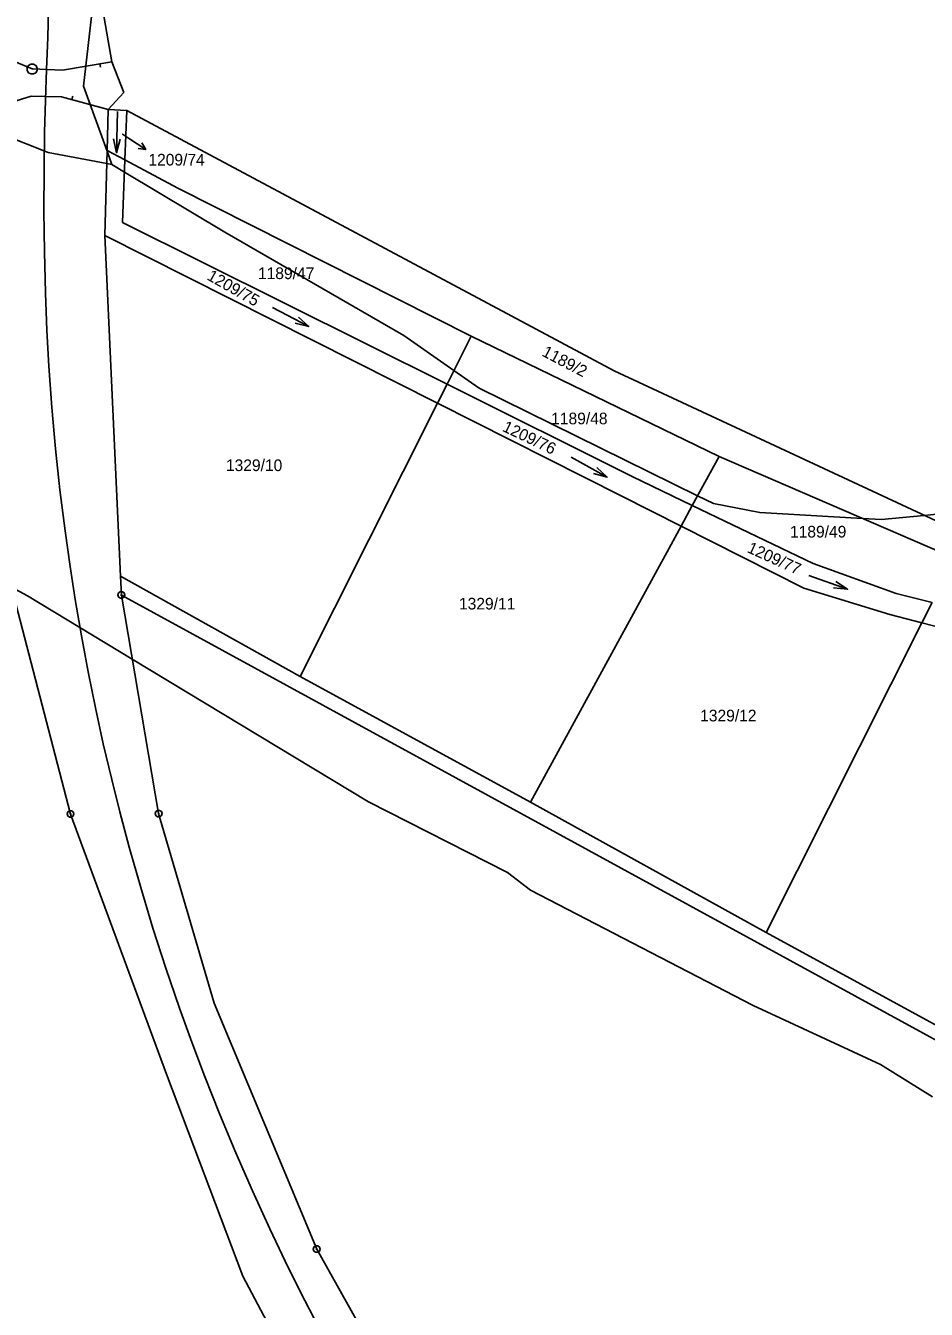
# Model space of a CAD drawing. Extents: x -789470 to -786707, y -1118640 to -1114455.
# Drawn here: x -787706 to -787574.7, y -1116838.5 to -1116651.3 of the extents above; entities that cross this region are included whole.
import ezdxf

# ---------------------------------------------------------------- set-up
doc = ezdxf.new("R2010")
doc.units = 0
for name, color, linetype in [('1', 7, 'Continuous'), ('11', 7, 'Continuous'), ('13', 7, 'Continuous'), ('2', 7, 'Continuous'), ('3', 7, 'Continuous'), ('6', 7, 'Continuous'), ('7', 7, 'Continuous'), ('8', 7, 'Continuous')]:
    doc.layers.add(name, color=color, linetype=linetype)

msp = doc.modelspace()

# ---------------------------------------------------------------- linework, layer by layer
at = {"layer": '1'}
for p, q in [((-787693.44, -1116656.57), (-787695.13, -1116646.88)), ((-787691.68, -1116661.08), (-787693.44, -1116656.57)), ((-787693.98, -1116663.52), (-787691.68, -1116661.08)), ((-787694.14, -1116669.51), (-787693.98, -1116663.52)), ((-787693.98, -1116663.52), (-787691.26, -1116663.69)), ((-787691.26, -1116663.69), (-787691.54, -1116670.9)), ((-787620.18, -1116701.66), (-787691.26, -1116663.69)), ((-787694.47, -1116681.92), (-787694.14, -1116669.51)), ((-787694.14, -1116669.51), (-787691.54, -1116670.9)), ((-787691.54, -1116670.9), (-787691.9, -1116680.01)), ((-787691.54, -1116670.9), (-787683.83, -1116675.03)), ((-787683.83, -1116675.03), (-787641.02, -1116696.6)), ((-787691.9, -1116680.01), (-787644.55, -1116703.62)), ((-787692.19, -1116731.59), (-787694.47, -1116681.92)), ((-787694.47, -1116681.92), (-787645.94, -1116706.39)), ((-787641.02, -1116696.6), (-787644.55, -1116703.62)), ((-787641.02, -1116696.6), (-787604.89, -1116714.14)), ((-787566.04, -1116726.9), (-787620.18, -1116701.66)), ((-787644.55, -1116703.62), (-787645.94, -1116706.39)), ((-787644.55, -1116703.62), (-787617.56, -1116717.08)), ((-787645.94, -1116706.39), (-787665.96, -1116746.26)), ((-787645.94, -1116706.39), (-787619.16, -1116719.89)), ((-787604.89, -1116714.14), (-787608.79, -1116721.29)), ((-787604.89, -1116714.14), (-787570.53, -1116728.97)), ((-787617.56, -1116717.08), (-787608.79, -1116721.29)), ((-787619.16, -1116719.89), (-787610.43, -1116724.3)), ((-787608.79, -1116721.29), (-787610.43, -1116724.3)), ((-787608.79, -1116721.29), (-787591.18, -1116729.74)), ((-787610.43, -1116724.3), (-787632.39, -1116764.58)), ((-787610.43, -1116724.3), (-787592.5, -1116733.37)), ((-787591.18, -1116729.74), (-787579.06, -1116734.12)), ((-787665.96, -1116746.26), (-787692.19, -1116731.59)), ((-787692.06, -1116734.36), (-787692.19, -1116731.59)), ((-787592.5, -1116733.37), (-787579.96, -1116737.21)), ((-787566.04, -1116803.25), (-787692.06, -1116734.36)), ((-787686.63, -1116766.25), (-787692.06, -1116734.36)), ((-787579.06, -1116734.12), (-787573.79, -1116735.43)), ((-787573.79, -1116735.43), (-787575.29, -1116738.41)), ((-787707.44, -1116735.64), (-787699.48, -1116766.3)), ((-787579.96, -1116737.21), (-787575.29, -1116738.41)), ((-787575.29, -1116738.41), (-787598.03, -1116783.56)), ((-787575.29, -1116738.41), (-787546.01, -1116745.93)), ((-787632.39, -1116764.58), (-787665.96, -1116746.26)), ((-787598.03, -1116783.56), (-787632.39, -1116764.58)), ((-787699.48, -1116766.3), (-787685.49, -1116804.26)), ((-787678.51, -1116793.87), (-787686.63, -1116766.25)), ((-787564.65, -1116801.84), (-787598.03, -1116783.56)), ((-787663.57, -1116829.76), (-787678.51, -1116793.87)), ((-787685.49, -1116804.26), (-787674.36, -1116833.72)), ((-787646.12, -1116860.74), (-787663.57, -1116829.76)), ((-787674.36, -1116833.72), (-787653.7, -1116872.34))]:
    msp.add_line(p, q, dxfattribs=at)
at = {"layer": '11'}
for points in [[(-787693.43, -1116671.58), (-787694.19, -1116671.43), (-787702.73, -1116669.8), (-787712.93, -1116665.78), (-787750.01, -1116651.19), (-787761.1, -1116647.27), (-787763.53, -1116646.41), (-787769.34, -1116643.04), (-787790.93, -1116630.52), (-787799.79, -1116626.21), (-787809.71, -1116621.47)], [(-787696.22, -1116648.29), (-787697.58, -1116660.12), (-787694.14, -1116669.61), (-787693.43, -1116671.58)], [(-787466.76, -1116688.14), (-787500, -1116682.32), (-787501.54, -1116682.05), (-787515.69, -1116684.6), (-787519.49, -1116685.93), (-787526.3, -1116688.31), (-787533.54, -1116692.9), (-787534.66, -1116693.74), (-787542.48, -1116699.58), (-787561.24, -1116718.02), (-787567.61, -1116720.5), (-787573.13, -1116722.56), (-787574.97, -1116722.74), (-787581.18, -1116723.33), (-787583.95, -1116723.18), (-787598.96, -1116722.33), (-787605.72, -1116721), (-787608.02, -1116719.87), (-787639.89, -1116704.2), (-787643.55, -1116701.62), (-787650.84, -1116696.49), (-787676.99, -1116681.45), (-787691.61, -1116672.67), (-787693.43, -1116671.58)], [(-787758.46, -1116706.09), (-787742.14, -1116714.87), (-787708.07, -1116733.22), (-787705.74, -1116734.47), (-787690.47, -1116743.7), (-787656, -1116764.52), (-787635.75, -1116774.85), (-787632.38, -1116777.42), (-787599.9, -1116794.21), (-787581.34, -1116802.84), (-787573.75, -1116807.56)]]:
    msp.add_lwpolyline(points, dxfattribs=at)
at = {"layer": '13'}
for p, q in [((-787711.9, -1116654.76), (-787705.05, -1116657.63)), ((-787700.64, -1116657.78), (-787693.44, -1116656.57)), ((-787695.22, -1116656.87), (-787695.13, -1116657.36)), ((-787693.44, -1116656.57), (-787691.68, -1116661.08)), ((-787705.05, -1116657.63), (-787700.64, -1116657.78)), ((-787705.21, -1116661.61), (-787713, -1116663.97)), ((-787700.79, -1116661.69), (-787705.21, -1116661.61)), ((-787693.98, -1116663.52), (-787700.79, -1116661.69)), ((-787699.29, -1116662.09), (-787699.16, -1116661.61)), ((-787691.68, -1116661.08), (-787693.98, -1116663.52))]:
    msp.add_line(p, q, dxfattribs=at)
at = {"layer": '3'}
for p, q in [((-787692.65, -1116663.84), (-787692.77, -1116669.84)), ((-787670.02, -1116692.4), (-787664.72, -1116695.2)), ((-787626.45, -1116714.24), (-787621.21, -1116717.18)), ((-787591.78, -1116731.5), (-787586.14, -1116733.52))]:
    msp.add_line(p, q, dxfattribs=at)
for points in [[(-787692.23, -1116667.85), (-787692.77, -1116669.84), (-787693.23, -1116667.83)], [(-787666.25, -1116693.83), (-787664.72, -1116695.2), (-787666.72, -1116694.71)], [(-787622.71, -1116715.76), (-787621.21, -1116717.18), (-787623.2, -1116716.64)], [(-787587.85, -1116732.38), (-787586.14, -1116733.52), (-787588.19, -1116733.32)]]:
    msp.add_lwpolyline(points, dxfattribs=at)
at = {"layer": '6'}
msp.add_line((-787702.06, -1116625.08), (-787702.77, -1116653), dxfattribs=at)
for points in [[(-787702.77, -1116653), (-787702.99, -1116657.73), (-787703.14, -1116662.17), (-787703.26, -1116666.91), (-787703.34, -1116672.4), (-787703.35, -1116678.36), (-787703.27, -1116684.32), (-787703.12, -1116690.27), (-787702.91, -1116695.76)], [(-787702.91, -1116695.76), (-787702.63, -1116700.98), (-787702.2, -1116707), (-787701.66, -1116713.02), (-787701.02, -1116719.02), (-787700.27, -1116725.02), (-787699.54, -1116730.19), (-787698.79, -1116735.02), (-787697.89, -1116740.3), (-787696.91, -1116745.56), (-787695.84, -1116750.81), (-787694.7, -1116756.05), (-787693.47, -1116761.26), (-787692.28, -1116766)], [(-787692.28, -1116766), (-787690.92, -1116771.12), (-787689.24, -1116777.04), (-787687.45, -1116782.93), (-787685.56, -1116788.79), (-787683.57, -1116794.62), (-787681.77, -1116799.6), (-787679.92, -1116804.51), (-787677.7, -1116810.14), (-787675.37, -1116815.73), (-787672.95, -1116821.28), (-787670.43, -1116826.79), (-787668.17, -1116831.52)], [(-787668.17, -1116831.52), (-787665.94, -1116836.02), (-787663.36, -1116841.02), (-787660.71, -1116845.97), (-787657.98, -1116850.88), (-787655.16, -1116855.74), (-787652.27, -1116860.56), (-787649.62, -1116864.83), (-787646.87, -1116869.14), (-787643.67, -1116873.96), (-787640.4, -1116878.73), (-787637.04, -1116883.45), (-787633.61, -1116888.11), (-787630.1, -1116892.71), (-787626.94, -1116896.72)]]:
    msp.add_lwpolyline(points, dxfattribs=at)
at = {"layer": '7'}
for p in [(-787691.92, -1116667.15), (-787688.51, -1116669.37)]:
    msp.add_line(p, (-787691.02, -1116667.73), dxfattribs=at)
msp.add_lwpolyline([(-787689.07, -1116668.4), (-787688.51, -1116669.37), (-787689.62, -1116669.24)], dxfattribs=at)
at = {"layer": '8'}
for p, q in [((-787705.1, -1116657.63), (-787705, -1116657.63)), ((-787692.18, -1116734.36), (-787691.94, -1116734.36)), ((-787699.6, -1116766.3), (-787699.36, -1116766.3)), ((-787686.75, -1116766.25), (-787686.51, -1116766.25)), ((-787663.69, -1116829.76), (-787663.45, -1116829.76))]:
    msp.add_line(p, q, dxfattribs=at)
for points in [[(-787704.86, -1116656.91), (-787704.52, -1116657.1), (-787704.33, -1116657.44), (-787704.33, -1116657.83), (-787704.52, -1116658.17), (-787704.86, -1116658.36), (-787705.25, -1116658.36), (-787705.59, -1116658.17), (-787705.78, -1116657.83), (-787705.78, -1116657.44), (-787705.59, -1116657.1), (-787705.25, -1116656.91)], [(-787691.91, -1116733.88), (-787691.66, -1116734.06), (-787691.56, -1116734.35), (-787691.66, -1116734.64), (-787691.91, -1116734.82), (-787692.22, -1116734.82), (-787692.47, -1116734.64), (-787692.57, -1116734.35), (-787692.47, -1116734.06), (-787692.22, -1116733.88)], [(-787699.33, -1116765.82), (-787699.08, -1116766), (-787698.98, -1116766.29), (-787699.08, -1116766.58), (-787699.33, -1116766.76), (-787699.64, -1116766.76), (-787699.89, -1116766.58), (-787699.99, -1116766.29), (-787699.89, -1116766), (-787699.64, -1116765.82)], [(-787686.48, -1116765.77), (-787686.23, -1116765.95), (-787686.13, -1116766.24), (-787686.23, -1116766.53), (-787686.48, -1116766.71), (-787686.79, -1116766.71), (-787687.04, -1116766.53), (-787687.14, -1116766.24), (-787687.04, -1116765.95), (-787686.79, -1116765.77)], [(-787663.42, -1116829.28), (-787663.17, -1116829.46), (-787663.07, -1116829.75), (-787663.17, -1116830.04), (-787663.42, -1116830.22), (-787663.73, -1116830.22), (-787663.98, -1116830.04), (-787664.08, -1116829.75), (-787663.98, -1116829.46), (-787663.73, -1116829.28)]]:
    msp.add_lwpolyline(points, close=True, dxfattribs=at)

# ---------------------------------------------------------------- texts
at = {"layer": '2'}
for s, height, p in [('1209/74', 0.1, (-787692.19, -1116667.15)), ('1189/47', 1.7, (-787672.14, -1116688.28)), ('1189/48', 1.7, (-787629.37, -1116709.46)), ('1329/10', 1.7, (-787676.81, -1116716.28)), ('1189/49', 1.7, (-787594.54, -1116725.97)), ('1329/11', 1.7, (-787642.82, -1116736.47)), ('1329/12', 1.7, (-787607.64, -1116752.79))]:
    msp.add_text(s, height=height, dxfattribs=at).set_placement(p)
for s, rotation, p in [('1209/75', 330.5394, (-787679.7, -1116688.28)), ('1189/2', 332.2582, (-787630.85, -1116699.4)), ('1209/76', 334.5501, (-787636.61, -1116710.39)), ('1209/77', 335.6387, (-787600.91, -1116728.07))]:
    msp.add_text(s, height=1.7, rotation=rotation, dxfattribs=at).set_placement(p)
at = {"layer": '7'}
msp.add_text('1209/74', height=1.7, dxfattribs=at).set_placement((-787688.12, -1116671.71))

doc.saveas('drawing.dxf')
